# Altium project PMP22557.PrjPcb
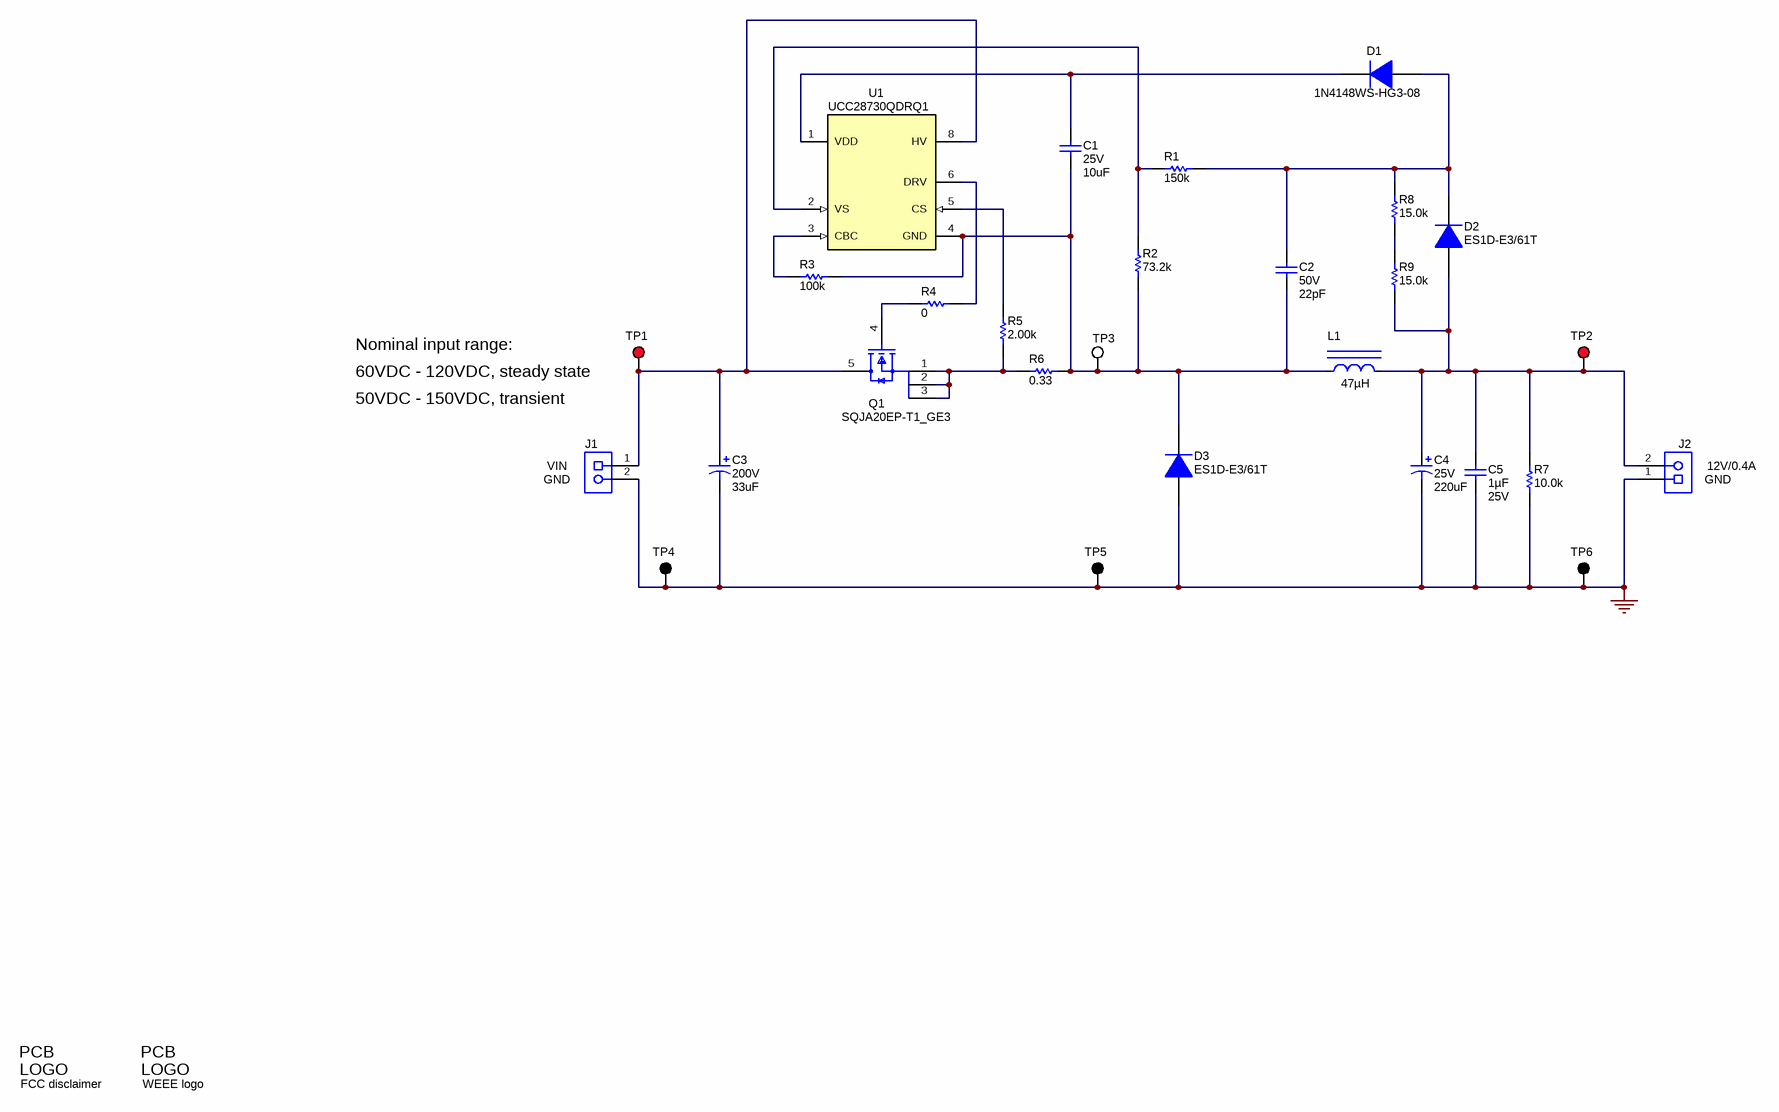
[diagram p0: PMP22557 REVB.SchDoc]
CopyrightYear: 2020; PCB_Layout: J Betten; PCB_Rev: A; PRJ_Customer: Public Release; PRJ_Engineer: J Betten; PRJ_Number: PMP22557; PRJ_Title: High Voltage buck with UCC28730; SCH_Rev: B; TechSupport: http://www.ti.com/support; TID: N/A
1 sheet, 30 parts. Net scope: global (net labels, ports and power ports of the same name join across sheets).
Board file: PMP22557_PCB.PcbDoc

## Sheet PMP22557 REVB.SchDoc
size 431 x 279 mm; Date: Not shown in title block; ApprovedBy: Not shown in title block; CheckedBy: Not shown in title block; Author: Not shown in title block; CompanyName: Not shown in title block; Engineer: Not shown in title block; Organization: Not shown in title block; Address1: Not shown in title block; Address2: Not shown in title block; Address3: Not shown in title block; Address4: Not shown in title block; DocumentNumber: 1; Revision: Use project parameter SCH_Rev; SheetNumber: 1; SheetTotal: 1; PageSetup: Record=PageOptions¦CenterHorizontal=True¦CenterVertical=True¦PrintScale=1.00¦XCorrection=1.00¦YCorrection=1.00¦PrintKind=0¦BorderSize=5000000¦LeftOffset=0¦BottomOffset=0¦Orientation=2¦PaperLength=1000¦PaperWidth=1000¦Scale=100¦PaperSource=15¦PrintQuality=600¦MediaType=1¦DitherType=10¦PaperKind=Letter¦PrintScaleMode=1

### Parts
C1  VDC_V: 25V  ValueDisplayed: 10uF  [1206_190]  (hidden comment: GCM31CC71E106KA03L)
C2  VDC_V: 50V  ValueDisplayed: 22pF  [0603]  (hidden comment: CGA3E2C0G1H220J080AA)
C3  VDC_V: 200V  ValueDisplayed: 33uF  [CS_1250x2000]  (hidden comment: UCS2E470MHD1TO)
C4  VDC_V: 25V  ValueDisplayed: 220uF  [SM_RADIAL_8MM]  (hidden comment: EEHZA1E221P)
C5  Cap_F: 1µF  VDC_V: 25V  [0603]  (hidden comment: GCM188R71E105KA64D)
D1  1N4148WS-HG3-08  [SOD-323]
D2  ES1D-E3/61T  [SMA]
D3  ES1D-E3/61T  [SMA]
J1  ED555/2DS  [TERM_BLK_ED555-2DS]  (value not drawn)
J2  ED555/2DS  [TERM_BLK_ED555-2DS]  (value not drawn)
L1  Ind_H: 47µH  [FP-SPM7054VT- 470M-D_STM_7MM5_7MM0-0]  (hidden comment: SPM7054VT-470M-D)
Logo1  FCC disclaimer  [FCC_disclaimer]  (no BOM)
Logo2  WEEE logo  [WEEE_Minimum]  (no BOM)
Q1  SQJA20EP-T1_GE3  [FP-SQJA20EP-T1_GE3_PowerPAK SO-8L Single-MFG]
R1  ValueDisplayed: 150k  [0402]  (hidden comment: CRCW0402150KFKED)
R2  ValueDisplayed: 73.2k  [0402]  (hidden comment: CRCW040273K2FKED)
R3  ValueDisplayed: 100k  [0402]  (hidden comment: CRCW0402100KFKED)
R4  ValueDisplayed: 0  [0402]  (hidden comment: ERJ-2GE0R00X)
R5  ValueDisplayed: 2.00k  [0402]  (hidden comment: CRCW04022K00FKED)
R6  ValueDisplayed: 0.33  [1206]  (hidden comment: ERJ-8RQFR33V)
R7  ValueDisplayed: 10.0k  [0603]  (hidden comment: CRCW060310K0FKEA)
R8  ValueDisplayed: 15.0k  [0805_HV]  (hidden comment: CRCW080515K0FKEA)
R9  ValueDisplayed: 15.0k  [0805_HV]  (hidden comment: CRCW080515K0FKEA)
TP1  5000  [Keystone5000]  (value not drawn)
TP2  5000  [Keystone5000]  (value not drawn)
TP3  5002  [Keystone5002]  (value not drawn)
TP4  5001  [Keystone5001]  (value not drawn)
TP5  5001  [Keystone5001]  (value not drawn)
TP6  5001  [Keystone5001]  (value not drawn)
U1  UCC28730QDRQ1  [D0007A_N]

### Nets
GND: C3.2(-) C4.2(-) C5.2 D3.2(A) J1.2 J2.1 R7.1 TP4.1 TP5.1 TP6.1
NetC1_1: C1.1 D1.1(K) U1.1(VDD)
NetC1_2: C1.2 C2.2 D3.1(K) L1.1 R2.1 R3.2 R6.2 TP3.1 U1.4(GND)
NetC2_1: C2.1 D1.2(A) D2.1(K) R1.2 R8.2
NetC3_1: C3.1(+) J1.1 Q1.5(D) TP1.1 U1.8(HV)
NetC4_1: C4.1(+) C5.1 D2.2(A) J2.2 L1.2 R7.2 R9.1 TP2.1
NetQ1_1: Q1.1(S) Q1.2(S) Q1.3(S) R5.1 R6.1
NetQ1_4: Q1.4(G) R4.2
NetR1_1: R1.1 R2.2 U1.2(VS)
NetR3_1: R3.1 U1.3(CBC)
NetR4_1: R4.1 U1.6(DRV)
NetR5_2: R5.2 U1.5(CS)
NetR8_1: R8.1 R9.2

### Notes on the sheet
- Nominal input range:
- (near TP1) 60VDC - 120VDC, steady state
- 50VDC - 150VDC, transient
- (near J1) VIN
- (near J1) GND
- (near J2) GND
- (near J2) 12V/0.4A

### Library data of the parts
C1 = CMP-0008807-2: CAP, CERM, 10 uF, 25 V, +/- 10%, X7S, AEC-Q200 Grade 1, 1206_190; Manufacturer: MuRata; TaMin_C: -55°C; Polarized: N; SizeAreaWB_mm2: 10.92; Value1: Unknown; U/M: EA; Value: 10uF; TaMax_C: 125°C; SizeZ_mm: 1.9; SizeX_mm: 3.2; SizeY_mm: 1.6; Cap_Case: 1206; SizeArea_mm2: 5.12; AEC Qualified: Y; Cap_F: 10µF; AEC Grade: 1; AEC Category: Q200
C2 = CMP-0007071-4: CAP, CERM, 22 pF, 50 V, +/- 5%, C0G/NP0, AEC-Q200 Grade 1, 0603; Manufacturer: TDK; TaMin_C: -55°C; Polarized: N; SizeAreaWB_mm2: 4.68; Value1: Unknown; U/M: EA; Value: 22pF; TaMax_C: 125°C; SizeZ_mm: 1; SizeX_mm: 1.6; SizeY_mm: 0.8; SizeArea_mm2: 1.28; AEC Qualified: Y; AEC Category: Q200
C3 = CMP-0010238-2: CAP, AL, 33 uF, 200 V, +/- 20%, TH; Manufacturer: Nichicon; TaMin_C: -40°C; Polarized: Y; SizeAreaWB_mm2: 210.25; Value1: Unknown; U/M: EA; Value: 33uF; TaMax_C: 150°C; SizeZ_mm: 21.5; SizeX_mm: 12.5; Cap_Case: 12.5x20mm; SizeArea_mm2: 156.25; CompType: Capacitor; AEC Qualified: N; Cap_F: 33µF; IRMS_A: 368mA; AEC Category: Q200
C4 = CMP-0012571-3: CAP, Polymer Hybrid, 220 uF, 25 V, +/- 20%, 27 ohm, 8x10 SMD; Manufacturer: Panasonic; TaMin_C: -55°C; ESR_ohm: 27; Polarized: Y; SizeAreaWB_mm2: 113.3; Value1: 27 ohm; Value: 220uF; TaMax_C: 105°C; SizeZ_mm: 10.2; SizeX_mm: 9; SizeY_mm: 8.3; SizeArea_mm2: 74.7; CompType: Capacitor; Cap_F: 220µF; IRMS_A: 2.3A; AEC Category: Q200
C5 = CMP-0007139-4: CAP, CERM, 1 uF, 25 V, +/- 10%, X7R, AEC-Q200 Grade 1, 0603; Manufacturer: MuRata; TaMin_C: -55°C; Polarized: N; SizeAreaWB_mm2: 4.68; Value1: Unknown; U/M: EA; Value: 1uF; TaMax_C: 125°C; SizeZ_mm: 1; SizeX_mm: 1.6; SizeY_mm: 0.8; SizeArea_mm2: 1.28; AEC Qualified: Y; AEC Category: Q200
D1 = CMP-0860225-1: Diode, Switching, 100 V, 150 A, AEC-Q101, SOD-323; Manufacturer: Vishay-Semiconductor; Vf_V: 1.2V; TJmax_C: 150°C; Value: 100V; SizeX_mm: 2.7; SizeZ_mm: 1; Io_A: 150A; SizeAreaWB_mm2: 8.695; AEC Qualified: Y; SizeY_mm: 1.35; SizeArea_mm2: 3.645; AEC Category: Q101
D2 D3 = CMP-0082147-2: Diode, Ultrafast, 200 V, 1 A, AEC-Q101, SMA; Manufacturer: Vishay-Semiconductor; SizeAreaWB_mm2: 37.3428; AEC Qualified: Y; SizeY_mm: 2.92; AEC Category: Q101; SizeArea_mm2: 16.3228; Io_A: 1A; Value2: 0.92V; SizeZ_mm: 2.87; SizeX_mm: 5.59; TJmax_C: 150°C; Vf_V: 920mV; Vr_V: 200V; Value: 200V
J1 J2 = CMP-0074913-1: Terminal Block, 3.5mm Pitch, 2x1, TH; Manufacturer: On-Shore Technology; Cert_VDE: Y; CNHeader: False; Current_A: 6A; Green_Lifecycle: Active; Shrouded: N; Gender: Female; Green_REACh: Passed; Voltage_V: 150V; Row_Count: 1; Pitch_mm: 3.5; ContactFinish: Brass; CT: True
L1 = CMP-0088010-1: Inductor, Shielded, Metal, 47 µH, 2.5 Arms, 0.162 ohm, AEC-Q200, SMD; Manufacturer: TDK; Symbol Name: SYM-SPM7054VT- 470M-D; AEC Grade: Grade 0; DCR_ohm: 0.1672; AEC Qualified: Yes; SizeZ_mm: 5.4mm; Isat: 3.6A
Logo1 = CMP-0074847-1: FCC_disclaimer; Library Reference: Logo
Logo2 = CMP-0074769-1
Q1 = CMP-0087405-1: MOSFET N-CH 200V PWRPAK SO-8L; Manufacturer: Vishay; IdsMax_A: 22.5A; Rdson45_ohm: 0.041; QgTyp_nC: 17.6nC @ 10V; Vgs_V: 20V; AEC Qualified: Yes; ChMode: False; SizeZ_mm: 1.267mm
R1 = CMP-0026021-3: RES, 150 k, 1%, 0.063 W, AEC-Q200 Grade 0, 0402; Manufacturer: Vishay-Dale; Power_W: 63mW; TempCo: 100 ppm/C; Value: 150k; EIA_Code: E96; SizeX_mm: 1; SizeY_mm: 0.5; SizeZ_mm: 0.6; Value2: 0.063W; AEC Qualified: Y; VDC_V: 50V; AEC Category: Q200; AEC Grade: 0
R2 = CMP-0026539-2: RES, 73.2 k, 1%, 0.063 W, AEC-Q200 Grade 0, 0402; Manufacturer: Vishay-Dale; Power_W: 63mW; TempCo: 100 ppm/C; Value_Code: 73k2; Value: 73.2k; EIA_Code: E96; SizeX_mm: 1; SizeY_mm: 0.5; SizeZ_mm: 0.6; Value2: 0.063W; AEC Qualified: Y; VDC_V: 50V; AEC Category: Q200; AEC Grade: 0
R3 = CMP-0025950-3: RES, 100 k, 1%, 0.063 W, AEC-Q200 Grade 0, 0402; Manufacturer: Vishay-Dale; Power_W: 63mW; TempCo: 100 ppm/C; Value: 100k; EIA_Code: E96; SizeX_mm: 1; SizeY_mm: 0.5; SizeZ_mm: 0.6; Value2: 0.063W; AEC Qualified: Y; VDC_V: 50V; AEC Category: Q200; AEC Grade: 0
R4 = CMP-0026992-3: RES, 0, 5%, 0.1 W, AEC-Q200 Grade 0, 0402; Manufacturer: Panasonic; Power_W: 100mW; TempCo: 600 ppm/C; Value_Code: 0000; Value: 0; EIA_Code: E24; SizeX_mm: 1; SizeY_mm: 0.5; SizeZ_mm: 0.6; Value2: 0.1W; AEC Qualified: Y; VDC_V: 50V; AEC Category: Q200; SizeAreaWB_mm2: 3
R5 = CMP-0026227-2: RES, 2.00 k, 1%, 0.063 W, AEC-Q200 Grade 0, 0402; Manufacturer: Vishay-Dale; Power_W: 63mW; TempCo: 100 ppm/C; Value_Code: 2k00; Value: 2.00k; EIA_Code: E96; Res_ohm: 2k; SizeX_mm: 1; SizeY_mm: 0.5; SizeZ_mm: 0.6; Value2: 0.063W; AEC Qualified: Y; VDC_V: 50V; AEC Category: Q200; AEC Grade: 0
R6 = CMP-0017788-3: RES, 0.33, 1%, 0.25 W, AEC-Q200 Grade 0, 1206; Manufacturer: Panasonic; Power_W: 250mW; TempCo: 250 ppm/C; Value_Code: R330; Value: 0.33; EIA_Code: E96; SizeX_mm: 3.2; SizeY_mm: 1.6; SizeZ_mm: 1.35; Value2: 0.25W; SizeArea_mm2: 5.12; AEC Qualified: Y; AEC Category: Q200; AEC Grade: 0; SizeAreaWB_mm2: 10.92
R7 = CMP-0021998-4: RES, 10.0 k, 1%, 0.1 W, AEC-Q200 Grade 0, 0603; Manufacturer: Vishay-Dale; Power_W: 100mW; TempCo: 100 ppm/C; Value_Code: 10k0; Value: 10.0k; EIA_Code: E96; Res_ohm: 10k; SizeX_mm: 1.6; SizeY_mm: 0.8; SizeZ_mm: 1; Value2: 0.1W; SizeArea_mm2: 1.28; AEC Qualified: Y; VDC_V: 75V; AEC Category: Q200; AEC Grade: 0
R8 R9 = CMP-0020909-3: RES, 15.0 k, 1%, 0.125 W, AEC-Q200 Grade 0, 0805; Manufacturer: Vishay-Dale; Power_W: 125mW; TempCo: 100 ppm/C; Value_Code: 15k0; Value: 15.0k; EIA_Code: E96; Res_ohm: 15k; SizeX_mm: 2; SizeY_mm: 1.25; SizeZ_mm: 1.45; Value2: 0.125W; SizeArea_mm2: 2.5; AEC Qualified: Y; VDC_V: 150V; AEC Category: Q200; AEC Grade: 0
TP1 TP2 = CMP-0055137-1: Test Point, Miniature, Red, TH; Manufacturer: Keystone; CNHeader: FALSE; ContactFinish: Silver; CT: TRUE; Green_Lifecycle: Active; Green_REACh: Passed
TP3 = CMP-0055139-1: Test Point, Miniature, White, TH; Manufacturer: Keystone; CNHeader: FALSE; Green_Lifecycle: Active; Green_REACh: Passed; ContactFinish: Silver; CT: TRUE
TP4-TP6 = CMP-0055138-1: Test Point, Miniature, Black, TH; Manufacturer: Keystone; CNHeader: FALSE; ContactFinish: Silver; CT: TRUE; Green_Lifecycle: Active; Green_REACh: Passed
U1 = CMP-0065056-3: Zero Standby PSR Flyback Controller with CVCC and Wake-Up Monitoring, Automotive, D0007A (SOIC-7); Manufacturer: Texas Instruments; SizeX_mm: 6.0; SizeY_mm: 4.9; CompType: IC; SizeZ_mm: 1.75; SizeArea_mm2: 29.4; SizeAreaWB_mm2: 55.2; U/M: EA; AEC Category: Q200; AEC Qualified: N

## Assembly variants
001: not fitted C2 R3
